// Mitsubishi GX Works2 project: 手轮   PLC: FX3U/FX3UC

PROGRAM MAIN
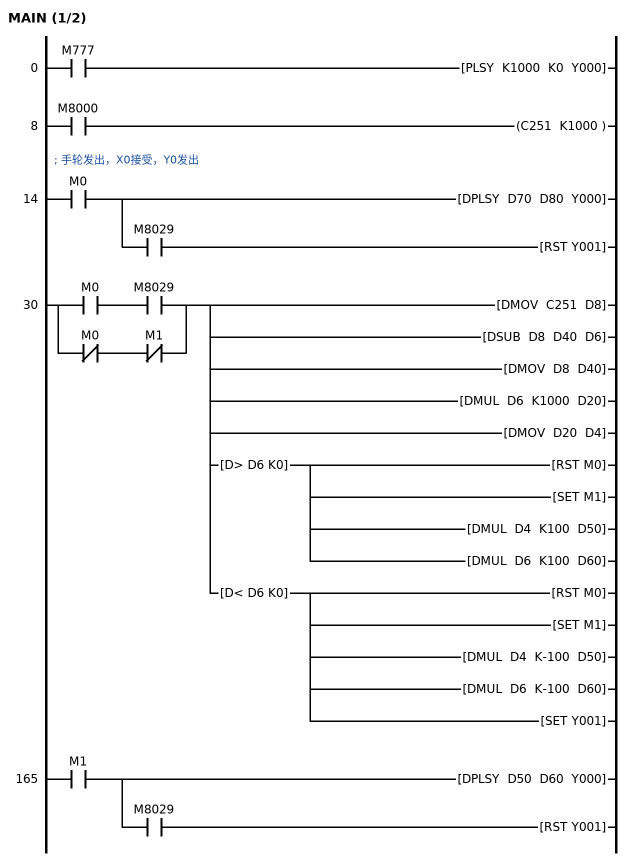
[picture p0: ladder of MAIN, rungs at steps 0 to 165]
0     LD      M777
      PLSY    K1000 K0 Y000
8     LD      M8000
      OUT     C251 K1000
        [note] 接收脉冲,X0/X1
; 手轮发出，X0接受，Y0发出
14    LD      M0
      DPLSY   D70 D80 Y000
      AND     M8029
      RST     Y001
30    LD      M0
      AND     M8029
      LDI     M0
      ANI     M1
      ORB
      DMOV    C251 D8
      DSUB    D8 D40 D6
      DMOV    D8 D40
      DMUL    D6 K1000 D20
      DMOV    D20 D4
      MPS
      ANDD>   D6 K0
      RST     M0
      SET     M1
      DMUL    D4 K100 D50
      DMUL    D6 K100 D60
      MPP
      ANDD<   D6 K0
      RST     M0
      SET     M1
      DMUL    D4 K-100 D50
      DMUL    D6 K-100 D60
      SET     Y001
165   LD      M1
      DPLSY   D50 D60 Y000
      AND     M8029
      RST     Y001
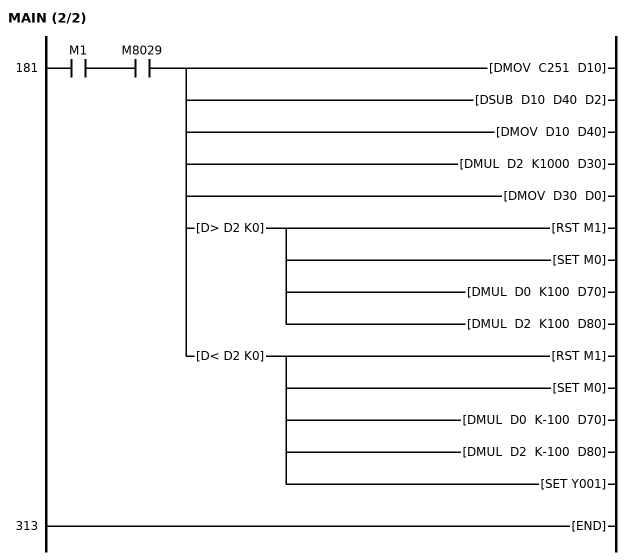
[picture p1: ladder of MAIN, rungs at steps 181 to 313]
181   LD      M1
      AND     M8029
      DMOV    C251 D10
      DSUB    D10 D40 D2
      DMOV    D10 D40
      DMUL    D2 K1000 D30
      DMOV    D30 D0
      MPS
      ANDD>   D2 K0
      RST     M1
      SET     M0
      DMUL    D0 K100 D70
      DMUL    D2 K100 D80
      MPP
      ANDD<   D2 K0
      RST     M1
      SET     M0
      DMUL    D0 K-100 D70
      DMUL    D2 K-100 D80
      SET     Y001
313   END
END_PROGRAM
